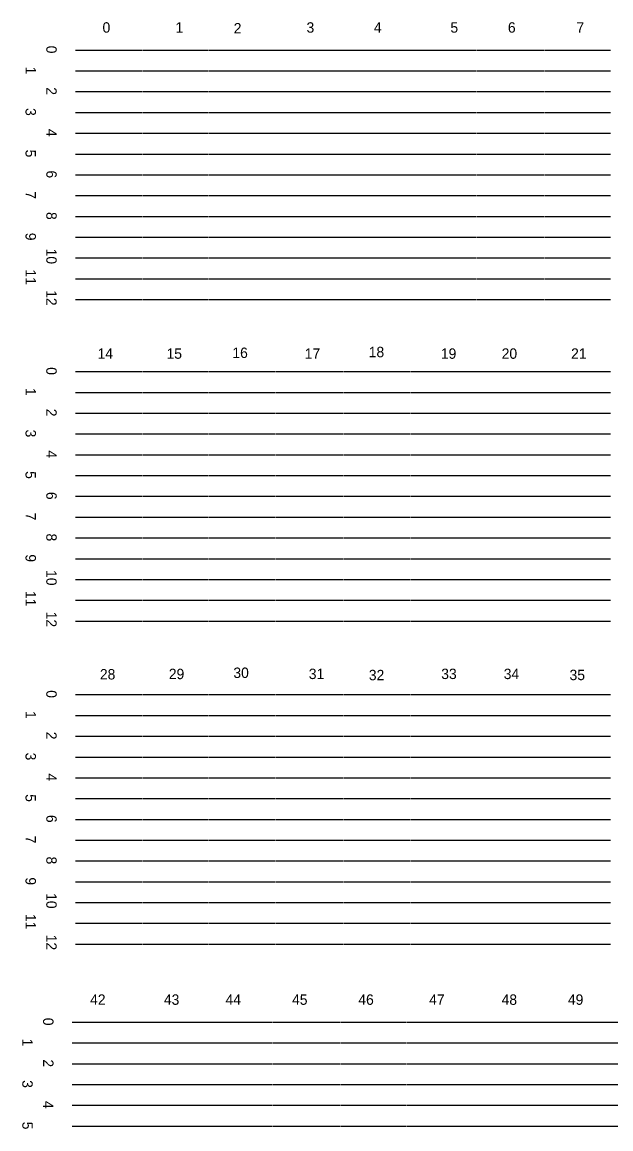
# Model space of a CAD drawing. Extents: x 11193 to 12507, y 10092 to 10555.
# Drawn here: x 11193.1 to 11315.8, y 10324.2 to 10554.9 of the extents above; entities that cross this region are included whole.
import ezdxf

# ---------------------------------------------------------------- set-up
doc = ezdxf.new("R2010")
doc.units = 0
doc.layers.add('Level 2', color=7, linetype='Continuous')

msp = doc.modelspace()

# ---------------------------------------------------------------- linework, layer by layer
at = {"layer": 'Level 2'}
for p, q in [((11204.21, 10549.04), (11218.13, 10549.04)), ((11218.23, 10549.04), (11231.81, 10549.04)), ((11231.91, 10549.04), (11245.89, 10549.04)), ((11245.99, 10549.04), (11259.97, 10549.04)), ((11260.08, 10549.04), (11273.85, 10549.04)), ((11273.96, 10549.04), (11287.73, 10549.04)), ((11287.84, 10549.04), (11301.81, 10549.04)), ((11301.92, 10549.04), (11315.7, 10549.04)), ((11204.21, 10544.71), (11218.13, 10544.71)), ((11218.23, 10544.71), (11231.81, 10544.71)), ((11231.91, 10544.71), (11245.89, 10544.71)), ((11245.99, 10544.71), (11259.97, 10544.71)), ((11260.08, 10544.71), (11273.85, 10544.71)), ((11273.96, 10544.71), (11287.73, 10544.71)), ((11287.84, 10544.71), (11301.81, 10544.71)), ((11301.92, 10544.71), (11315.7, 10544.71)), ((11204.21, 10540.38), (11218.13, 10540.38)), ((11218.23, 10540.38), (11231.81, 10540.38)), ((11231.91, 10540.38), (11245.89, 10540.38)), ((11245.99, 10540.38), (11259.97, 10540.38)), ((11260.08, 10540.38), (11273.85, 10540.38)), ((11273.96, 10540.38), (11287.73, 10540.38)), ((11287.84, 10540.38), (11301.81, 10540.38)), ((11301.92, 10540.38), (11315.7, 10540.38)), ((11204.21, 10536.05), (11218.13, 10536.05)), ((11218.23, 10536.05), (11231.81, 10536.05)), ((11231.91, 10536.05), (11245.89, 10536.05)), ((11245.99, 10536.05), (11259.97, 10536.05)), ((11260.08, 10536.05), (11273.85, 10536.05)), ((11273.96, 10536.05), (11287.73, 10536.05)), ((11287.84, 10536.05), (11301.81, 10536.05)), ((11301.92, 10536.05), (11315.7, 10536.05)), ((11204.21, 10531.72), (11218.13, 10531.72)), ((11218.23, 10531.72), (11231.81, 10531.72)), ((11231.91, 10531.72), (11245.89, 10531.72)), ((11245.99, 10531.72), (11259.97, 10531.72)), ((11260.08, 10531.72), (11273.85, 10531.72)), ((11273.96, 10531.72), (11287.73, 10531.72)), ((11287.84, 10531.72), (11301.81, 10531.72)), ((11301.92, 10531.72), (11315.7, 10531.72)), ((11204.21, 10527.38), (11218.13, 10527.38)), ((11218.23, 10527.38), (11231.81, 10527.38)), ((11231.91, 10527.38), (11245.89, 10527.38)), ((11245.99, 10527.38), (11259.97, 10527.38)), ((11260.08, 10527.38), (11273.85, 10527.38)), ((11273.96, 10527.38), (11287.73, 10527.38)), ((11287.84, 10527.38), (11301.81, 10527.38)), ((11301.92, 10527.38), (11315.7, 10527.38)), ((11204.21, 10523.05), (11218.13, 10523.05)), ((11218.23, 10523.05), (11231.81, 10523.05)), ((11231.91, 10523.05), (11245.89, 10523.05)), ((11245.99, 10523.05), (11259.97, 10523.05)), ((11260.08, 10523.05), (11273.85, 10523.05)), ((11273.96, 10523.05), (11287.73, 10523.05)), ((11287.84, 10523.05), (11301.81, 10523.05)), ((11301.92, 10523.05), (11315.7, 10523.05)), ((11204.21, 10518.72), (11218.13, 10518.72)), ((11218.23, 10518.72), (11231.81, 10518.72)), ((11231.91, 10518.72), (11245.89, 10518.72)), ((11245.99, 10518.72), (11259.97, 10518.72)), ((11260.08, 10518.72), (11273.85, 10518.72)), ((11273.96, 10518.72), (11287.73, 10518.72)), ((11287.84, 10518.72), (11301.81, 10518.72)), ((11301.92, 10518.72), (11315.7, 10518.72)), ((11204.21, 10514.39), (11218.13, 10514.39)), ((11218.23, 10514.39), (11231.81, 10514.39)), ((11231.91, 10514.39), (11245.89, 10514.39)), ((11245.99, 10514.39), (11259.97, 10514.39)), ((11260.08, 10514.39), (11273.85, 10514.39)), ((11273.96, 10514.39), (11287.73, 10514.39)), ((11287.84, 10514.39), (11301.81, 10514.39)), ((11301.92, 10514.39), (11315.7, 10514.39)), ((11204.21, 10510.06), (11218.13, 10510.06)), ((11218.23, 10510.06), (11231.81, 10510.06)), ((11231.91, 10510.06), (11245.89, 10510.06)), ((11245.99, 10510.06), (11259.97, 10510.06)), ((11260.08, 10510.06), (11273.85, 10510.06)), ((11273.96, 10510.06), (11287.73, 10510.06)), ((11287.84, 10510.06), (11301.81, 10510.06)), ((11301.92, 10510.06), (11315.7, 10510.06)), ((11204.21, 10505.72), (11218.13, 10505.72)), ((11218.23, 10505.72), (11231.81, 10505.72)), ((11231.91, 10505.72), (11245.89, 10505.72)), ((11245.99, 10505.72), (11259.97, 10505.72)), ((11260.08, 10505.72), (11273.85, 10505.72)), ((11273.96, 10505.72), (11287.73, 10505.72)), ((11287.84, 10505.72), (11301.81, 10505.72)), ((11301.92, 10505.72), (11315.7, 10505.72)), ((11204.21, 10501.39), (11218.13, 10501.39)), ((11218.23, 10501.39), (11231.81, 10501.39)), ((11231.91, 10501.39), (11245.89, 10501.39)), ((11245.99, 10501.39), (11259.97, 10501.39)), ((11260.08, 10501.39), (11273.85, 10501.39)), ((11273.96, 10501.39), (11287.73, 10501.39)), ((11287.84, 10501.39), (11301.81, 10501.39)), ((11301.92, 10501.39), (11315.7, 10501.39)), ((11204.21, 10497.06), (11218.13, 10497.06)), ((11218.23, 10497.06), (11231.81, 10497.06)), ((11231.91, 10497.06), (11245.89, 10497.06)), ((11245.99, 10497.06), (11259.97, 10497.06)), ((11260.08, 10497.06), (11273.85, 10497.06)), ((11273.96, 10497.06), (11287.73, 10497.06)), ((11287.84, 10497.06), (11301.81, 10497.06)), ((11301.92, 10497.06), (11315.7, 10497.06)), ((11204.21, 10482.04), (11218.14, 10482.04)), ((11218.26, 10482.04), (11231.82, 10482.04)), ((11231.93, 10482.04), (11245.9, 10482.04)), ((11246.02, 10482.04), (11259.98, 10482.04)), ((11260.1, 10482.04), (11273.87, 10482.04)), ((11273.98, 10482.04), (11287.75, 10482.04)), ((11287.85, 10482.04), (11301.83, 10482.04)), ((11301.93, 10482.04), (11315.71, 10482.04)), ((11204.21, 10477.71), (11218.14, 10477.71)), ((11218.26, 10477.71), (11231.82, 10477.71)), ((11231.93, 10477.71), (11245.9, 10477.71)), ((11246.02, 10477.71), (11259.98, 10477.71)), ((11260.1, 10477.71), (11273.87, 10477.71)), ((11273.98, 10477.71), (11287.75, 10477.71)), ((11287.85, 10477.71), (11301.83, 10477.71)), ((11301.93, 10477.71), (11315.71, 10477.71)), ((11204.21, 10473.37), (11218.14, 10473.37)), ((11218.26, 10473.37), (11231.82, 10473.37)), ((11231.93, 10473.37), (11245.9, 10473.37)), ((11246.02, 10473.37), (11259.98, 10473.37)), ((11260.1, 10473.37), (11273.87, 10473.37)), ((11273.98, 10473.37), (11287.75, 10473.37)), ((11287.85, 10473.37), (11301.83, 10473.37)), ((11301.93, 10473.37), (11315.71, 10473.37)), ((11204.21, 10469.04), (11218.14, 10469.04)), ((11218.26, 10469.04), (11231.82, 10469.04)), ((11231.93, 10469.04), (11245.9, 10469.04)), ((11246.02, 10469.04), (11259.98, 10469.04)), ((11260.1, 10469.04), (11273.87, 10469.04)), ((11273.98, 10469.04), (11287.75, 10469.04)), ((11287.85, 10469.04), (11301.83, 10469.04)), ((11301.93, 10469.04), (11315.71, 10469.04)), ((11204.21, 10464.71), (11218.14, 10464.71)), ((11218.26, 10464.71), (11231.82, 10464.71)), ((11231.93, 10464.71), (11245.9, 10464.71)), ((11246.02, 10464.71), (11259.98, 10464.71)), ((11260.1, 10464.71), (11273.87, 10464.71)), ((11273.98, 10464.71), (11287.75, 10464.71)), ((11287.85, 10464.71), (11301.83, 10464.71)), ((11301.93, 10464.71), (11315.71, 10464.71)), ((11204.21, 10460.38), (11218.14, 10460.38)), ((11218.26, 10460.38), (11231.82, 10460.38)), ((11231.93, 10460.38), (11245.9, 10460.38)), ((11246.02, 10460.38), (11259.98, 10460.38)), ((11260.1, 10460.38), (11273.87, 10460.38)), ((11273.98, 10460.38), (11287.75, 10460.38)), ((11287.85, 10460.38), (11301.83, 10460.38)), ((11301.93, 10460.38), (11315.71, 10460.38)), ((11204.21, 10456.05), (11218.14, 10456.05)), ((11218.26, 10456.05), (11231.82, 10456.05)), ((11231.93, 10456.05), (11245.9, 10456.05)), ((11246.02, 10456.05), (11259.98, 10456.05)), ((11260.1, 10456.05), (11273.87, 10456.05)), ((11273.98, 10456.05), (11287.75, 10456.05)), ((11287.85, 10456.05), (11301.83, 10456.05)), ((11301.93, 10456.05), (11315.71, 10456.05)), ((11204.21, 10451.71), (11218.14, 10451.71)), ((11218.26, 10451.71), (11231.82, 10451.71)), ((11231.93, 10451.71), (11245.9, 10451.71)), ((11246.02, 10451.71), (11259.98, 10451.71)), ((11260.1, 10451.71), (11273.87, 10451.71)), ((11273.98, 10451.71), (11287.75, 10451.71)), ((11287.85, 10451.71), (11301.83, 10451.71)), ((11301.93, 10451.71), (11315.71, 10451.71)), ((11204.21, 10447.38), (11218.14, 10447.38)), ((11218.26, 10447.38), (11231.82, 10447.38)), ((11231.93, 10447.38), (11245.9, 10447.38)), ((11246.02, 10447.38), (11259.98, 10447.38)), ((11260.1, 10447.38), (11273.87, 10447.38)), ((11273.98, 10447.38), (11287.75, 10447.38)), ((11287.85, 10447.38), (11301.83, 10447.38)), ((11301.93, 10447.38), (11315.71, 10447.38)), ((11204.21, 10443.05), (11218.14, 10443.05)), ((11218.26, 10443.05), (11231.82, 10443.05)), ((11231.93, 10443.05), (11245.9, 10443.05)), ((11246.02, 10443.05), (11259.98, 10443.05)), ((11260.1, 10443.05), (11273.87, 10443.05)), ((11273.98, 10443.05), (11287.75, 10443.05)), ((11287.85, 10443.05), (11301.83, 10443.05)), ((11301.93, 10443.05), (11315.71, 10443.05)), ((11204.21, 10438.72), (11218.14, 10438.72)), ((11218.26, 10438.72), (11231.82, 10438.72)), ((11231.93, 10438.72), (11245.9, 10438.72)), ((11246.02, 10438.72), (11259.98, 10438.72)), ((11260.1, 10438.72), (11273.87, 10438.72)), ((11273.98, 10438.72), (11287.75, 10438.72)), ((11287.85, 10438.72), (11301.83, 10438.72)), ((11301.93, 10438.72), (11315.71, 10438.72)), ((11204.21, 10434.39), (11218.14, 10434.39)), ((11218.26, 10434.39), (11231.82, 10434.39)), ((11231.93, 10434.39), (11245.9, 10434.39)), ((11246.02, 10434.39), (11259.98, 10434.39)), ((11260.1, 10434.39), (11273.87, 10434.39)), ((11273.98, 10434.39), (11287.75, 10434.39)), ((11287.85, 10434.39), (11301.83, 10434.39)), ((11301.93, 10434.39), (11315.71, 10434.39)), ((11204.21, 10430.05), (11218.14, 10430.05)), ((11218.26, 10430.05), (11231.82, 10430.05)), ((11231.93, 10430.05), (11245.9, 10430.05)), ((11246.02, 10430.05), (11259.98, 10430.05)), ((11260.1, 10430.05), (11273.87, 10430.05)), ((11273.98, 10430.05), (11287.75, 10430.05)), ((11287.85, 10430.05), (11301.83, 10430.05)), ((11301.93, 10430.05), (11315.71, 10430.05)), ((11204.21, 10414.72), (11218.14, 10414.72)), ((11218.26, 10414.72), (11231.82, 10414.72)), ((11231.93, 10414.72), (11245.9, 10414.72)), ((11246.02, 10414.72), (11259.98, 10414.72)), ((11260.1, 10414.72), (11273.87, 10414.72)), ((11273.98, 10414.72), (11287.75, 10414.72)), ((11287.85, 10414.72), (11301.83, 10414.72)), ((11301.93, 10414.72), (11315.71, 10414.72)), ((11204.21, 10410.39), (11218.14, 10410.39)), ((11218.26, 10410.39), (11231.82, 10410.39)), ((11231.93, 10410.39), (11245.9, 10410.39)), ((11246.02, 10410.39), (11259.98, 10410.39)), ((11260.1, 10410.39), (11273.87, 10410.39)), ((11273.98, 10410.39), (11287.75, 10410.39)), ((11287.85, 10410.39), (11301.83, 10410.39)), ((11301.93, 10410.39), (11315.71, 10410.39)), ((11204.21, 10406.06), (11218.14, 10406.06)), ((11218.26, 10406.06), (11231.82, 10406.06)), ((11231.93, 10406.06), (11245.9, 10406.06)), ((11246.02, 10406.06), (11259.98, 10406.06)), ((11260.1, 10406.06), (11273.87, 10406.06)), ((11273.98, 10406.06), (11287.75, 10406.06)), ((11287.85, 10406.06), (11301.83, 10406.06)), ((11301.93, 10406.06), (11315.71, 10406.06)), ((11204.21, 10401.72), (11218.14, 10401.72)), ((11218.26, 10401.72), (11231.82, 10401.72)), ((11231.93, 10401.72), (11245.9, 10401.72)), ((11246.02, 10401.72), (11259.98, 10401.72)), ((11260.1, 10401.72), (11273.87, 10401.72)), ((11273.98, 10401.72), (11287.75, 10401.72)), ((11287.85, 10401.72), (11301.83, 10401.72)), ((11301.93, 10401.72), (11315.71, 10401.72)), ((11204.21, 10397.39), (11218.14, 10397.39)), ((11218.26, 10397.39), (11231.82, 10397.39)), ((11231.93, 10397.39), (11245.9, 10397.39)), ((11246.02, 10397.39), (11259.98, 10397.39)), ((11260.1, 10397.39), (11273.87, 10397.39)), ((11273.98, 10397.39), (11287.75, 10397.39)), ((11287.85, 10397.39), (11301.83, 10397.39)), ((11301.93, 10397.39), (11315.71, 10397.39)), ((11204.21, 10393.06), (11218.14, 10393.06)), ((11218.26, 10393.06), (11231.82, 10393.06)), ((11231.93, 10393.06), (11245.9, 10393.06)), ((11246.02, 10393.06), (11259.98, 10393.06)), ((11260.1, 10393.06), (11273.87, 10393.06)), ((11273.98, 10393.06), (11287.75, 10393.06)), ((11287.85, 10393.06), (11301.83, 10393.06)), ((11301.93, 10393.06), (11315.71, 10393.06)), ((11204.21, 10388.73), (11218.14, 10388.73)), ((11218.26, 10388.73), (11231.82, 10388.73)), ((11231.93, 10388.73), (11245.9, 10388.73)), ((11246.02, 10388.73), (11259.98, 10388.73)), ((11260.1, 10388.73), (11273.87, 10388.73)), ((11273.98, 10388.73), (11287.75, 10388.73)), ((11287.85, 10388.73), (11301.83, 10388.73)), ((11301.93, 10388.73), (11315.71, 10388.73)), ((11204.21, 10384.4), (11218.14, 10384.4)), ((11218.26, 10384.4), (11231.82, 10384.4)), ((11231.93, 10384.4), (11245.9, 10384.4)), ((11246.02, 10384.4), (11259.98, 10384.4)), ((11260.1, 10384.4), (11273.87, 10384.4)), ((11273.98, 10384.4), (11287.75, 10384.4)), ((11287.85, 10384.4), (11301.83, 10384.4)), ((11301.93, 10384.4), (11315.71, 10384.4)), ((11204.21, 10380.06), (11218.14, 10380.06)), ((11218.26, 10380.06), (11231.82, 10380.06)), ((11231.93, 10380.06), (11245.9, 10380.06)), ((11246.02, 10380.06), (11259.98, 10380.06)), ((11260.1, 10380.06), (11273.87, 10380.06)), ((11273.98, 10380.06), (11287.75, 10380.06)), ((11287.85, 10380.06), (11301.83, 10380.06)), ((11301.93, 10380.06), (11315.71, 10380.06)), ((11204.21, 10375.73), (11218.14, 10375.73)), ((11218.26, 10375.73), (11231.82, 10375.73)), ((11231.93, 10375.73), (11245.9, 10375.73)), ((11246.02, 10375.73), (11259.98, 10375.73)), ((11260.1, 10375.73), (11273.87, 10375.73)), ((11273.98, 10375.73), (11287.75, 10375.73)), ((11287.85, 10375.73), (11301.83, 10375.73)), ((11301.93, 10375.73), (11315.71, 10375.73)), ((11204.21, 10371.4), (11218.14, 10371.4)), ((11218.26, 10371.4), (11231.82, 10371.4)), ((11231.93, 10371.4), (11245.9, 10371.4)), ((11246.02, 10371.4), (11259.98, 10371.4)), ((11260.1, 10371.4), (11273.87, 10371.4)), ((11273.98, 10371.4), (11287.75, 10371.4)), ((11287.85, 10371.4), (11301.83, 10371.4)), ((11301.93, 10371.4), (11315.71, 10371.4)), ((11204.21, 10367.07), (11218.14, 10367.07)), ((11218.26, 10367.07), (11231.82, 10367.07)), ((11231.93, 10367.07), (11245.9, 10367.07)), ((11246.02, 10367.07), (11259.98, 10367.07)), ((11260.1, 10367.07), (11273.87, 10367.07)), ((11273.98, 10367.07), (11287.75, 10367.07)), ((11287.85, 10367.07), (11301.83, 10367.07)), ((11301.93, 10367.07), (11315.71, 10367.07)), ((11204.21, 10362.74), (11218.14, 10362.74)), ((11218.26, 10362.74), (11231.82, 10362.74)), ((11231.93, 10362.74), (11245.9, 10362.74)), ((11246.02, 10362.74), (11259.98, 10362.74)), ((11260.1, 10362.74), (11273.87, 10362.74)), ((11273.98, 10362.74), (11287.75, 10362.74)), ((11287.85, 10362.74), (11301.83, 10362.74)), ((11301.93, 10362.74), (11315.71, 10362.74)), ((11203.54, 10346.46), (11217.46, 10346.46)), ((11217.56, 10346.46), (11231.14, 10346.46)), ((11231.24, 10346.46), (11245.22, 10346.46)), ((11245.32, 10346.46), (11259.3, 10346.46)), ((11259.41, 10346.46), (11273.18, 10346.46)), ((11273.29, 10346.46), (11287.06, 10346.46)), ((11287.17, 10346.46), (11301.14, 10346.46)), ((11301.25, 10346.46), (11315.03, 10346.46)), ((11315.14, 10346.46), (11329.11, 10346.46)), ((11203.54, 10342.13), (11217.46, 10342.13)), ((11217.56, 10342.13), (11231.14, 10342.13)), ((11231.24, 10342.13), (11245.22, 10342.13)), ((11245.32, 10342.13), (11259.3, 10342.13)), ((11259.41, 10342.13), (11273.18, 10342.13)), ((11273.29, 10342.13), (11287.06, 10342.13)), ((11287.17, 10342.13), (11301.14, 10342.13)), ((11301.25, 10342.13), (11315.03, 10342.13)), ((11315.14, 10342.13), (11329.11, 10342.13)), ((11203.54, 10337.8), (11217.46, 10337.8)), ((11217.56, 10337.8), (11231.14, 10337.8)), ((11231.24, 10337.8), (11245.22, 10337.8)), ((11245.32, 10337.8), (11259.3, 10337.8)), ((11259.41, 10337.8), (11273.18, 10337.8)), ((11273.29, 10337.8), (11287.06, 10337.8)), ((11287.17, 10337.8), (11301.14, 10337.8)), ((11301.25, 10337.8), (11315.03, 10337.8)), ((11315.14, 10337.8), (11329.11, 10337.8)), ((11203.54, 10333.47), (11217.46, 10333.47)), ((11217.56, 10333.47), (11231.14, 10333.47)), ((11231.24, 10333.47), (11245.22, 10333.47)), ((11245.32, 10333.47), (11259.3, 10333.47)), ((11259.41, 10333.47), (11273.18, 10333.47)), ((11273.29, 10333.47), (11287.06, 10333.47)), ((11287.17, 10333.47), (11301.14, 10333.47)), ((11301.25, 10333.47), (11315.03, 10333.47)), ((11315.14, 10333.47), (11329.11, 10333.47)), ((11203.54, 10329.14), (11217.46, 10329.14)), ((11217.56, 10329.14), (11231.14, 10329.14)), ((11231.24, 10329.14), (11245.22, 10329.14)), ((11245.32, 10329.14), (11259.3, 10329.14)), ((11259.41, 10329.14), (11273.18, 10329.14)), ((11273.29, 10329.14), (11287.06, 10329.14)), ((11287.17, 10329.14), (11301.14, 10329.14)), ((11301.25, 10329.14), (11315.03, 10329.14)), ((11315.14, 10329.14), (11329.11, 10329.14)), ((11203.54, 10324.8), (11217.46, 10324.8)), ((11217.56, 10324.8), (11231.14, 10324.8)), ((11231.24, 10324.8), (11245.22, 10324.8)), ((11245.32, 10324.8), (11259.3, 10324.8)), ((11259.41, 10324.8), (11273.18, 10324.8)), ((11273.29, 10324.8), (11287.06, 10324.8)), ((11287.17, 10324.8), (11301.14, 10324.8)), ((11301.25, 10324.8), (11315.03, 10324.8)), ((11315.14, 10324.8), (11329.11, 10324.8))]:
    msp.add_line(p, q, dxfattribs=at)

# ---------------------------------------------------------------- texts
for s, height, p in [('0', 2.17, (11209.85, 10552.67)), ('1', 2.17, (11225.04, 10552.67)), ('2', 2.17, (11237.18, 10552.51)), ('3', 2.17, (11252.35, 10552.67)), ('4', 2.17, (11266.38, 10552.67)), ('5', 2.17, (11282.33, 10552.67)), ('6', 2.17, (11294.31, 10552.67)), ('7', 2.17, (11308.59, 10552.67)), ('18', 2.166, (11265.31, 10485.04)), ('14', 2.166, (11208.8, 10484.71)), ('15', 2.166, (11223.18, 10484.71)), ('16', 2.166, (11236.9, 10484.88)), ('17', 2.166, (11251.98, 10484.71)), ('19', 2.166, (11280.34, 10484.71)), ('20', 2.166, (11293.01, 10484.71)), ('21', 2.166, (11307.47, 10484.71)), ('30', 2.166, (11237.11, 10418.2)), ('28', 2.166, (11209.3, 10417.88)), ('29', 2.166, (11223.66, 10417.95)), ('31', 2.166, (11252.82, 10417.97)), ('32', 2.166, (11265.33, 10417.72)), ('33', 2.166, (11280.42, 10417.97)), ('34', 2.166, (11293.44, 10417.96)), ('35', 2.166, (11307.15, 10417.74)), ('42', 2.17, (11207.25, 10350.08)), ('43', 2.17, (11222.63, 10350.08)), ('44', 2.17, (11235.47, 10350.08)), ('45', 2.17, (11249.33, 10350.08)), ('46', 2.17, (11263.14, 10350.08)), ('47', 2.17, (11277.9, 10350.08)), ('48', 2.17, (11292.99, 10350.08)), ('49', 2.17, (11306.8, 10350.08))]:
    msp.add_text(s, height=height, dxfattribs=at).set_placement(p)
for s, height, p in [('0', 2.17, (11198.13, 10549.96)), ('1', 2.17, (11193.8, 10545.62)), ('2', 2.17, (11198.13, 10541.29)), ('3', 2.17, (11193.8, 10536.96)), ('4', 2.17, (11198.13, 10532.63)), ('5', 2.17, (11193.8, 10528.3)), ('6', 2.17, (11198.13, 10523.96)), ('7', 2.17, (11193.8, 10519.63)), ('8', 2.17, (11198.13, 10515.3)), ('9', 2.17, (11193.8, 10510.97)), ('10', 2.166, (11198.13, 10507.67)), ('11', 2.166, (11193.8, 10503.34)), ('12', 2.166, (11198.13, 10499.01)), ('0', 2.17, (11198.13, 10482.96)), ('1', 2.17, (11193.8, 10478.63)), ('2', 2.17, (11198.13, 10474.3)), ('3', 2.17, (11193.8, 10469.96)), ('4', 2.17, (11198.13, 10465.63)), ('5', 2.17, (11193.8, 10461.3)), ('6', 2.17, (11198.13, 10456.97)), ('7', 2.17, (11193.8, 10452.64)), ('8', 2.17, (11198.13, 10448.3)), ('9', 2.17, (11193.8, 10443.97)), ('10', 2.166, (11198.13, 10440.68)), ('11', 2.166, (11193.8, 10436.34)), ('12', 2.166, (11198.13, 10432.01)), ('0', 2.17, (11198.13, 10415.64)), ('1', 2.17, (11193.8, 10411.31)), ('2', 2.17, (11198.13, 10406.98)), ('3', 2.17, (11193.8, 10402.64)), ('4', 2.17, (11198.13, 10398.31)), ('5', 2.17, (11193.8, 10393.98)), ('6', 2.17, (11198.13, 10389.65)), ('7', 2.17, (11193.8, 10385.32)), ('8', 2.17, (11198.13, 10380.98)), ('9', 2.17, (11193.8, 10376.65)), ('10', 2.166, (11198.13, 10373.36)), ('11', 2.166, (11193.8, 10369.02)), ('12', 2.166, (11198.13, 10364.69)), ('0', 2.17, (11197.46, 10347.38)), ('1', 2.17, (11193.13, 10343.04)), ('2', 2.17, (11197.46, 10338.71)), ('3', 2.17, (11193.13, 10334.38)), ('4', 2.17, (11197.46, 10330.05)), ('5', 2.17, (11193.13, 10325.72))]:
    msp.add_text(s, height=height, rotation=270, dxfattribs=at).set_placement(p)

doc.saveas('drawing.dxf')
